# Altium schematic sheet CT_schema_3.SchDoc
size 284 x 211 mm
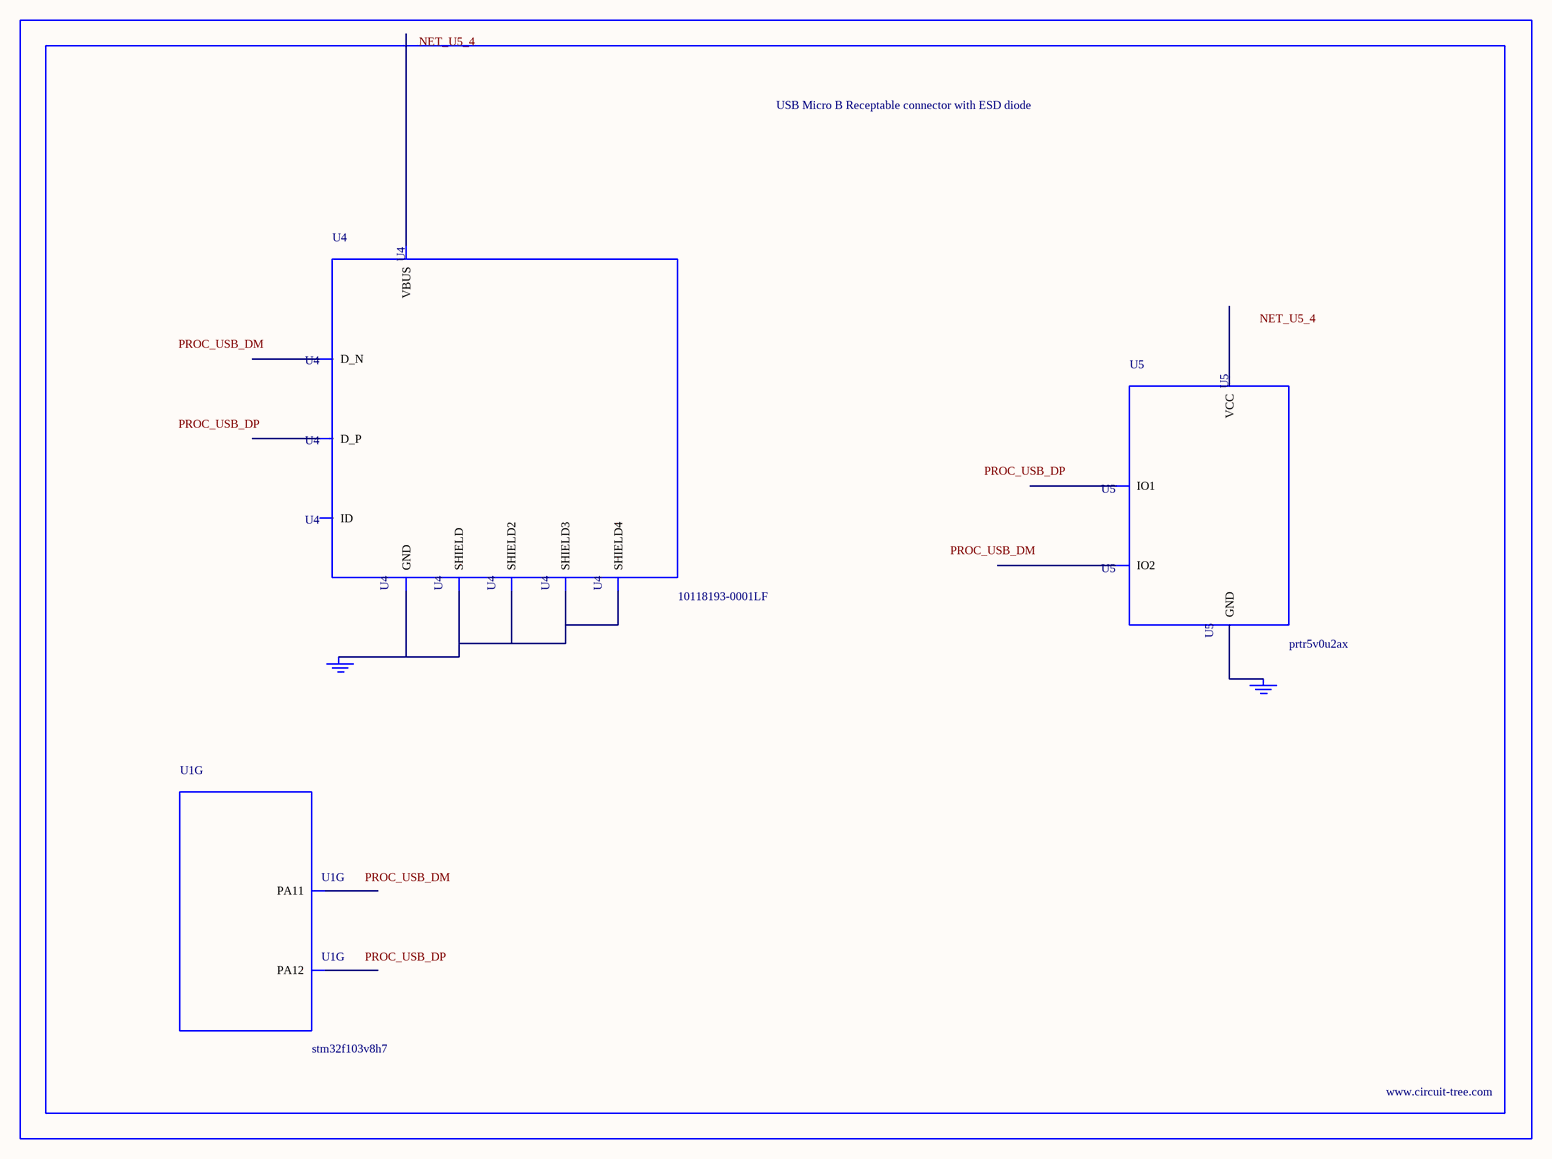
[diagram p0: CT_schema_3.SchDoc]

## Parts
BORDER2  (no value)
GND_INSTANCE_2_0  (no value)
GND_INSTANCE_2_1  (no value)
U1  stm32f103v8h7  [LFBGA100]  (part G of 9)
U4  10118193-0001LF  [FCI_10118193-0001LF]
U5  prtr5v0u2ax  [SOT143B]

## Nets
NetGND_INSTANCE_2_0_0: GND_INSTANCE_2_0.0(GND) U4.5(GND) U4.6(SHIELD) U4.7(SHIELD2) U4.8(SHIELD3) U4.9(SHIELD4)
NetGND_INSTANCE_2_1_0: GND_INSTANCE_2_1.0(GND) U5.1(GND)

Not connected (* = marked no-connect by the designer): U1 B10(PA12) C10(PA11); U4 1(VBUS) 2(D_N) 3(D_P) 4(ID); U5 2(IO1) 3(IO2) 4(VCC)

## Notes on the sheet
- Labels drawn without touching a wire or pin: NET_U5_4, PROC_USB_DM, PROC_USB_DP

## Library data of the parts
BORDER2 = BORDER_PAGE2
GND_INSTANCE_2_0 GND_INSTANCE_2_1 = GND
